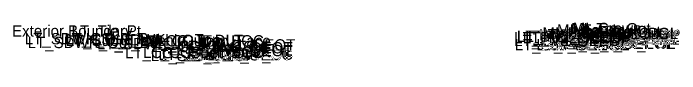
# Model space of a CAD drawing. Extents: x 0 to 6300, y 0 to 9528.
# Drawn here: x 3085.6 to 3144.7, y 1500.4 to 1504.1 of the extents above; entities that cross this region are included whole.
import ezdxf

# ---------------------------------------------------------------- set-up
doc = ezdxf.new("R2010")
doc.units = 0
doc.layers.add('Default', color=7, linetype='Continuous')

msp = doc.modelspace()

# ---------------------------------------------------------------- texts
at = {"layer": 'Default'}
for s, p in [('Exterior Boundary', (3085.451, 1502.834)), ('LT_Tie_Pt', (3090.732, 1502.834)), ('MI_Face In', (3132.551, 1502.658)), ('MI_Top In', (3133.839, 1502.908)), ('MI_Top Out', (3135.095, 1503.028)), ('MI_Crown', (3135.239, 1503.052)), ('MI_Face Out', (3135.307, 1502.778)), ('RT_PV1_PGL', (3136.135, 1502.611)), ('MI_Bot Out', (3136.498, 1502.611)), ('LT_SDWK_Out_Top', (3086.58, 1502.149)), ('LT_CSLP_Pnt', (3090.099, 1502.149)), ('LT_Sub_Trench_Out_DLT', (3090.209, 1502)), ('LT_SDWK_In_Top', (3092.738, 1502.049)), ('LT_CG_Top_BOC', (3096.81, 1501.959)), ('LT_CG_Top_Face', (3097.341, 1501.959)), ('LT_PV2_OEEOP', (3130.035, 1502.241)), ('LT_PV3_OEEOP', (3130.035, 1501.991)), ('LT_PV1_OEEOP', (3130.275, 1502.366)), ('LT_PV2_IEEOP', (3130.796, 1502.241)), ('LT_PV1_IEEOP', (3131.035, 1502.366)), ('LT_PV2_PGL1', (3131.635, 1502.241)), ('LT_PV3_PGL1', (3131.635, 1501.991)), ('LT_PV2_PGL', (3132.014, 1502.241)), ('LT_PV1_PGL', (3132.253, 1502.491)), ('MI_Bot In', (3133.721, 1502.491)), ('RT_PV2_OEEOP', (3133.917, 1502.361)), ('RT_PV3_OEEOP', (3133.917, 1502.111)), ('RT_PV1_OEEOP', (3134.157, 1502.486)), ('RT_PV2_IEEOP', (3134.678, 1502.361)), ('RT_PV1_IEEOP', (3134.917, 1502.486)), ('RT_PV2_PGL1', (3135.516, 1502.361)), ('RT_PV3_PGL1', (3135.516, 1502.111)), ('RT_PV2_PGL', (3135.895, 1502.361)), ('LT_SDWK_Out_Bot', (3086.829, 1501.815)), ('LT_SDWK_In_Bot', (3092.987, 1501.715)), ('LT_CG_Top_Gut', (3097.87, 1501.459)), ('LT_PV2_OEOT', (3100.991, 1501.349)), ('LT_PV1_OEOT', (3101.23, 1501.599)), ('LT_Sub_OEEOP', (3130.082, 1501.616)), ('LT_PV4_PGL', (3132.014, 1501.616)), ('RT_Sub_OEEOP', (3133.964, 1501.736)), ('RT_PV4_PGL', (3135.895, 1501.736)), ('LT_CG1_Shelf_Out', (3095.478, 1500.925)), ('LT_CG_Bot_BOC', (3097.088, 1500.94)), ('LT_Sub_OEOT_CG', (3098.436, 1500.765)), ('LT_PV3_OEOT', (3100.991, 1501.099)), ('LT_Sub_OEOT', (3101.038, 1500.724)), ('LT_CG_Bot_IE', (3101.339, 1501.015)), ('LT_Sub_OEOP', (3097.772, 1500.667))]:
    msp.add_text(s, height=1, dxfattribs=at).set_placement(p)

doc.saveas('drawing.dxf')
